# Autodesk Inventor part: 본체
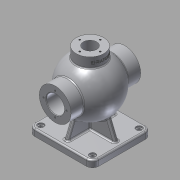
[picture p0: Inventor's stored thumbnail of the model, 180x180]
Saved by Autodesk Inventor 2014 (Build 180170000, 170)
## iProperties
Created: 2015-10
Part Number: 본체
Material: 알루미늄 6061
Document SubType Name: Modeling
Designer: youjin03
Density: 2.71 g/cm^3
Appearance: 알루미늄 - 평지
Mass: 1615.14 g
Surface Area: 1162.48 cm^2
Volume: 595.994 cm^3
Author: youjin03
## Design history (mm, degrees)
sketch "스케치1"
  geometry: L1 (50.5, 57.5)-(-50.5, 57.5); L2 (-62.5, 45.5)-(-62.5, -45.5); L3 (-50.5, -57.5)-(50.5, -57.5); L4 (62.5, -45.5)-(62.5, 45.5); L5 (62.5, 57.5)-(-62.5, -57.5); L6 (-62.5, 57.5)-(62.5, -57.5); C1 r 4 at (-50.5, -45.5); C2 r 4 at (50.5, -45.5); C3 r 4 at (50.5, 45.5); C4 r 4 at (-50.5, 45.5); A1 r 12 centre (-50.5, 45.5) between (-50.5, 57.5) and (-62.5, 45.5); A2 r 12 centre (-50.5, -45.5) between (-62.5, -45.5) and (-50.5, -57.5); A3 r 12 centre (50.5, -45.5) between (50.5, -57.5) and (62.5, -45.5); A4 r 12 centre (50.5, 45.5) between (62.5, 45.5) and (50.5, 57.5); 1 further point
  constraints: 12 end point, 8 centre point, 8 point on circle, 8 point on line, 8 tangent, 4 coincident, 3 equal radius, 2 midpoint, 2 parallel, 1 horizontal, 1 perpendicular
  dimensions: "d0" = 125 distance of L6.end L5.end; "d1" = 115 distance of L6.start L5.end; "d2" = 12 radius of A1; "d3" = 8 diameter of C1; "d4" = 8 diameter of C2; "d5" = 8 diameter of C3; "d6" = 8 diameter of C4
extrude "돌출1" new body sketch "스케치1" distance "d7" = 13; taper "d8" = 0 deg
sketch "스케치2"
  geometry: C1 r 4 at (-50.5, 45.5) reference; C2 r 4 at (50.5, 45.5) reference; C3 r 4 at (50.5, -45.5) reference; C4 r 4 at (-50.5, -45.5) reference; C5 r 6 at (-50.5, -45.5); C6 r 6 at (-50.5, 45.5); C7 r 6 at (50.5, 45.5); C8 r 6 at (50.5, -45.5); A1 r 12 centre (-50.5, -45.5) between (-62.5, -45.5) and (-50.5, -57.5) reference; A2 r 12 centre (50.5, -45.5) between (50.5, -57.5) and (62.5, -45.5) reference; A3 r 12 centre (50.5, 45.5) between (62.5, 45.5) and (50.5, 57.5) reference; A4 r 12 centre (-50.5, 45.5) between (-50.5, 57.5) and (-62.5, 45.5) reference; 1 further point
  constraints: 4 centre point, 4 coincident
  dimensions: "d9" = 12 diameter of C5; "d10" = 12 diameter of C6; "d11" = 12 diameter of C7; "d12" = 12 diameter of C8
extrude "돌출2" cut sketch "스케치2" distance "d13" = 3; taper "d14" = 0 deg
sketch "스케치3"
  geometry: L1 (35.892, 46.003)-(-35.892, 123.997); L2 (-50.5, 0)-(50.5, 0) reference; L3 (50.5, 0)-(-50.5, 0) reference; C1 r 53 at (0, 85); A1 r 53 centre (0, 85) between (35.892, 46.003) and (-35.892, 123.997); 3 further points
  constraints: 3 midpoint, 2 centre point, 2 end point, 2 point on circle, 1 coincident, 1 vertical alignment
  dimensions: "d15" = 106 diameter of C1; "d16" = 106 diameter of A1; "d18" = 85 distance from line of C1.centre L2
revolve "회전1" sketch "스케치3" stored, may be unused: angle "d17" = 90 deg
sketch "스케치6"
  geometry: C1 r 53 at (0, 85) reference; C2 r 31 at (0, 85); 1 further point
  constraints: 1 centre point, 1 coincident
  dimensions: "d19" = 62 diameter of C2
extrude "돌출3" join sketch "스케치6" stored distance "d20" = 136; taper "d21" = 0 deg
node "작업 평면1"
sketch "스케치7"
  geometry: C1 r 27 at (0, 0); 1 further point
  constraints: 1 centre point, 1 coincident
  dimensions: "d23" = 54 diameter of C1
extrude "돌출4" join sketch "스케치7" stored distance "d24" = 136; taper "d25" = 0 deg
sketch "스케치8"
  geometry: C1 r 31 at (0, 0) reference; C2 r 17.5 at (0, 0); 1 further point
  constraints: 1 centre point, 1 coincident
  dimensions: "d26" = 35 diameter of C2
extrude "돌출5" cut sketch "스케치8" distance "d27" = 118.25; taper "d28" = 0 deg
sketch "스케치9"
  geometry: C1 r 31 at (0, 0) reference; C2 r 17.5 at (0, 0); 1 further point
  constraints: 1 centre point, 1 coincident
  dimensions: "d29" = 35 diameter of C2
extrude "돌출6" cut sketch "스케치9" distance "d30" = 16; taper "d31" = 0 deg
sketch "스케치10"
  geometry: C1 r 17.5 at (0, 0) reference; C2 r 18.5 at (0, 0); 1 further point
  constraints: 1 centre point, 1 coincident
  dimensions: "d32" = 37 diameter of C2
extrude "돌출7" cut sketch "스케치10" distance "d33" = 1.75; taper "d34" = 0 deg
node "작업 평면3"
  node "작업 평면2"
sketch "스케치11"
  geometry: C1 r 31 at (0, 85) reference; C2 r 18.5 at (0, 85); C3 r 17.5 at (0, 85); 1 further point
  constraints: 2 centre point, 2 coincident
  dimensions: "d37" = 37 diameter of C2; "d38" = 35 diameter of C3
extrude "돌출8" cut sketch "스케치11" distance "d39" = 1.75; taper "d40" = 0 deg
sketch "스케치13"
  geometry: L1 (-42.988, 54)-(-42.988, 116) reference; L2 (42.988, 116)-(42.988, 54) reference; L3 (-27, 130.607)-(27, 130.607) reference; L4 (7.223, 127.389)-(-7.223, 42.611); C1 r 43 at (0, 85); A1 r 53 centre (0, 85) between (-42.988, 54) and (-42.988, 116) reference; A2 r 43 centre (0, 85) between (7.223, 127.389) and (-7.223, 42.611); 1 further point
  constraints: 2 centre point, 2 coincident, 2 end point, 2 point on circle, 1 midpoint
  dimensions: "d41" = 86 diameter of C1; "d42" = 86 diameter of A2
revolve "회전2" sketch "스케치13" stored, may be unused: angle "d43" = 90 deg
sketch "스케치14"
  geometry: C1 r 27 at (0, 0) reference; C2 r 13 at (0, 0)
  constraints: 1 centre point, 1 coincident
  dimensions: "d44" = 26 diameter of C2
extrude "돌출9" cut sketch "스케치14" stored distance "d45" = 1.75; taper "d46" = 0 deg
sketch "스케치15"
  geometry: C1 r 27 at (0, 0) reference; A1 r 20 centre (0, 0) between (0, 20) and (20, 0); 2 further points
  constraints: 4 point on circle, 1 centre point, 1 coincident
  dimensions: "d47" = 40 diameter of A1
hole "구멍1" sketch "스케치15" at (0, 20), (20, 0), (0, -20), (-20, 0) diameter "d48" = 3.242; stored, may be unused: countersink angle "d52" = 90 deg, drill point angle "d54" = 118 deg; dims "d49" = 9, "d50" = 4, "d51" = 2, "d53" = 11
sketch "스케치16"
  geometry: C1 r 31 at (0, 0) reference; A1 r 22.5 centre (0, 0) between (0, 22.5) and (22.5, 0); 3 further points
  constraints: 4 point on circle, 1 centre point, 1 coincident
  dimensions: "d55" = 45 diameter of A1
hole "구멍2" sketch "스케치16" at (0, 22.5), (22.5, 0), (0, -22.5), (-22.5, 0) diameter "d56" = 3.242; stored, may be unused: countersink angle "d60" = 90 deg, drill point angle "d62" = 118 deg; dims "d57" = 12, "d58" = 4, "d59" = 2, "d61" = 15
sketch "스케치17"
  geometry: C1 r 31 at (0, 0) reference; A1 r 24 centre (0, 0) between (0, 24) and (24, 0); 3 further points
  constraints: 4 point on circle, 1 centre point, 1 coincident
  dimensions: "d63" = 48 diameter of A1
hole "구멍3" sketch "스케치17" at (0, 24), (24, 0), (0, -24), (-24, 0) diameter "d64" = 3.242; stored, may be unused: countersink angle "d68" = 90 deg, drill point angle "d70" = 118 deg; dims "d65" = 16, "d66" = 4, "d67" = 2, "d69" = 19
sketch "스케치18"
  geometry: L1 (57.5, 13)-(45.5, 13) reference; L2 (39.5, 13)-(51.5, 13) reference; L3 (45.5, 13)-(-45.5, 13) reference; L4 (-51.5, 13)-(-39.5, 13) reference; L5 (-45.5, 13)-(-57.5, 13) reference; L6 (-68, 54)-(-42.988, 54) reference; L7 (42.988, 54)-(68, 54) reference; L8 (57.5, 13)-(47.5, 13); L9 (47.5, 13)-(34.623, 44.872); L10 (57.5, 0)-(57.5, 13) reference; L11 (-57.5, 13)-(-47.5, 13); L12 (-47.5, 13)-(-34.623, 44.872); L13 (-57.5, 0)-(-57.5, 13) reference; L14 (-47.5, 13)-(47.5, 13); A1 r 53 centre (0, 85) between (-42.988, 54) and (-42.988, 116) reference; A2 r 43 centre (0, 85) between (-39.278, 67.5) and (-39.278, 102.5) reference; 2 further points
  constraints: 10 end point, 2 point on circle, 2 point on line, 1 coincident, 1 perpendicular, 3 other
  dimensions: "d71" = 10 distance of L1.start L8.end; "d73" = 22 deg angle of L9 L10; "d74" = 10 distance of L5.end L11.end; "d75" = 22 deg angle of L12 L13
extrude "돌출10" join sketch "스케치18" stored distance "d76" = 8; taper "d77" = 0 deg
sketch "스케치19"
  geometry: L1 (50.5, 13)-(-50.5, 13) reference; L2 (62.5, 13)-(50.5, 13) reference; L3 (-56.5, 13)-(-44.5, 13) reference; L4 (-50.5, 13)-(-62.5, 13) reference; L5 (-62.5, 0)-(-62.5, 13) reference; L6 (62.5, 0)-(62.5, 13) reference; L7 (62.5, 13)-(52.5, 13); L8 (-62.5, 13)-(-52.5, 13); L9 (-52.5, 13)-(-34.03, 58.714); L10 (52.5, 13)-(34.03, 58.714); L11 (-52.5, 13)-(52.5, 13); C1 r 21.705 at (0, 85); A1 r 53 centre (0, 85) between (-27, 130.607) and (27, 130.607) reference; A2 r 53 centre (0, 85) between (-27, 130.607) and (27, 130.607) reference; A3 r 43 centre (0, 85) between (-13, 125.988) and (13, 125.988) reference; 1 further point
  constraints: 10 end point, 2 point on circle, 2 point on line, 1 centre point, 1 coincident, 1 collinear, 1 tangent
  dimensions: "d78" = 10 distance of L2.start L7.end; "d79" = 10 distance of L4.end L8.end; "d80" = 22 deg angle of L9 L5; "d82" = 22 deg angle of L10 L6
extrude "돌출11" join sketch "스케치19" stored distance "d83" = 8; taper "d84" = 0 deg
node "작업 평면5"
  node "작업 평면4"
sketch "스케치20"
  geometry: L1 (-27, 0)-(-27, -19.393) reference; L2 (-27, 0)-(27, 0) reference; 2 further points
  constraints: 1 other
  dimensions: "d86" = 10 distance from line of point (0, -10) L2; "d87" = 27 distance from line of L1 point (0, -10)
feature "엠보싱1" sketch "스케치20" dims "d88" = 0.5, "d89" = 0
chamfer "모따기1" distance "d90" = 1; stored, may be unused: second distance "d91" = 2, angle "d92" = 45 deg
chamfer "모따기2" distance "d93" = 1; stored, may be unused: second distance "d94" = 2, angle "d95" = 45 deg
fillet "모깎기1" dims "d96" = 3
node "작업 평면6"
sketch "스케치21"
  geometry: 1 further point
sketch "스케치22"
  geometry: L1 (38.176, 48.454)-(52.5, 13) reference; L2 (38.787, 46.941)-(38.238, 48.3); A1 r 53 centre (0, 85) between (38.238, 48.3) and (-38.238, 48.3) reference; 2 further points
  constraints: 2 end point, 1 point on circle, 1 point on line
node "작업 평면8"
  node "작업 평면7"
sketch "스케치23"
  geometry: 1 further point
sketch "스케치24"
  geometry: L1 (-47.5, 13)-(-34.623, 44.872) reference; L2 (34.623, 44.872)-(47.5, 13) reference; L3 (57.5, 13)-(45.5, 13) reference; L4 (-45.5, 13)-(-57.5, 13) reference; L5 (-47.5, 13)-(-32.825, 49.321); L6 (47.5, 13)-(33.835, 46.823); L7 (-32.825, 49.321)-(0, 33.153); L8 (0, 33.153)-(33.835, 46.823); L9 (-47.5, 13)-(47.5, 13); 1 further point
  constraints: 10 end point, 3 collinear, 1 perpendicular
extrude "돌출12" join sketch "스케치24" stored distance "d98" = 8; taper "d99" = 0 deg
fillet "모깎기2" dims "d100" = 3
node "솔리드1"
node "투영된 루프1"
other parameters: "d35" = 68, "d36" = -16, "d85" = 0.5, "d97" = 10.5
